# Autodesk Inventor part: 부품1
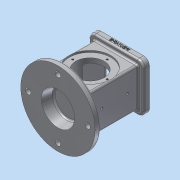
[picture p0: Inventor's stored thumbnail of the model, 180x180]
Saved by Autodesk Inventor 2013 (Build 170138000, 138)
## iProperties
Created: 2018-10
Part Number: 부품1
Material: 알루미늄 6061
Document SubType Name: Modeling
Designer: Administrator
Density: 2.71 g/cm^3
Mass: 988.226 g
Surface Area: 743.901 cm^2
Volume: 364.659 cm^3
Author: Administrator
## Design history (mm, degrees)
sketch "스케치1"
  geometry: L1 (37, 33)-(-37, 33); L2 (-37, 33)-(-37, -33); L3 (-37, -33)-(37, -33); L4 (37, -33)-(37, 33); L5 (37, 33)-(-37, -33); L6 (-37, 33)-(37, -33); 1 further point
  constraints: 12 end point, 2 midpoint, 2 parallel, 1 horizontal, 1 perpendicular
  dimensions: "d0" = 74 distance of L3.end L2.end; "d1" = 66 distance of L2.end L1.end
extrude "돌출1" new body sketch "스케치1" stored distance "d2" = 108; taper "d3" = 0 deg
sketch "스케치2"
  geometry: L1 (-37, -33)-(37, -33) reference; L2 (37, -33)-(37, 33) reference; L3 (37, 33)-(-37, 33) reference; L4 (-37, 33)-(-37, -33) reference; L5 (-46, -41)-(46, -41); L6 (46, -41)-(46, 41); L7 (46, 41)-(-46, 41); L8 (-46, 41)-(-46, -41); L9 (-46, -41)-(46, 41); L10 (46, -41)-(-46, 41); 1 further point
  constraints: 12 end point, 2 midpoint, 2 parallel, 1 horizontal, 1 perpendicular
  dimensions: "d4" = 92 distance of L7.end L6.end; "d5" = 82 distance of L6.end L5.end
extrude "돌출2" join sketch "스케치2" distance "d6" = 10; taper "d7" = 0 deg
sketch "스케치3"
  geometry: L1 (37, 33)-(-37, 33) reference; L2 (-37, 33)-(-37, -33) reference; L3 (-37, -33)-(37, -33) reference; L4 (37, -33)-(37, 33) reference; C1 r 62.5 at (0, 0); 1 further point
  constraints: 1 centre point, 1 coincident
  dimensions: "d8" = 125 diameter of C1
extrude "돌출3" join sketch "스케치3" distance "d9" = 10; taper "d10" = 0 deg
node "작업 평면1"
sketch "스케치4"
  geometry: C1 r 35 at (0, 0); 1 further point
  constraints: 1 centre point, 1 coincident
  dimensions: "d12" = 70 diameter of C1
extrude "돌출4" cut sketch "스케치4" distance "d13" = 3; taper "d14" = 0 deg
sketch "스케치5"
  geometry: C1 r 35 at (0, 0) reference; C2 r 24 at (0, 0)
  constraints: 1 centre point, 1 coincident
  dimensions: "d15" = 48 diameter of C2
extrude "돌출5" cut sketch "스케치5" stored distance "d16" = 3; taper "d17" = 0 deg
sketch "스케치6" dims "d18" = 58
  geometry: C1 r 35 at (0, 0) reference; 2 further points
  constraints: 2 vertical alignment, 1 coincident, 2 other
hole "구멍1" sketch "스케치6" at (0, 29) diameter "d19" = 3.242; stored, may be unused: countersink angle "d23" = 90 deg, drill point angle "d25" = 118 deg; dims "d20" = 4, "d21" = 4, "d22" = 2, "d24" = 6
sketch "스케치7"
  geometry: L1 (-26, -26)-(26, -26); L2 (26, -26)-(26, 26); L3 (26, 26)-(-26, 26); L4 (-26, 26)-(-26, -26); L5 (-26, -26)-(26, 26); L6 (26, -26)-(-26, 26); 1 further point
  constraints: 12 end point, 2 midpoint, 2 parallel, 1 horizontal, 1 perpendicular
  dimensions: "d29" = 52 distance of L3.end L2.end; "d30" = 52 distance of L2.end L1.end
extrude "돌출6" cut sketch "스케치7" distance "d31" = 8; taper "d32" = 0 deg
sketch "스케치8"
  geometry: L1 (-22, -22)-(22, -22); L2 (22, -22)-(22, 22); L3 (22, 22)-(-22, 22); L4 (-22, 22)-(-22, -22); L5 (-22, -22)-(22, 22); L6 (22, -22)-(-22, 22); 1 further point
  constraints: 12 end point, 2 midpoint, 2 parallel, 1 horizontal, 1 perpendicular
  dimensions: "d33" = 44 distance of L3.end L2.end; "d34" = 44 distance of L2.end L1.end
extrude "돌출7" cut sketch "스케치8" distance "d35" = 74; taper "d36" = 0 deg
sketch "스케치9"
  geometry: L1 (-46, 44)-(-46, 54) reference; L2 (-46, 54)-(-26, 54) reference; L3 (-26, 54)-(-26, 46) reference; L4 (-26, 46)-(-22, 46) reference; L5 (-22, 46)-(-22, 9.592) reference; L6 (-22, -9.592)-(-22, -28) reference; L7 (-22, -28)-(22, -28) reference; L8 (22, -28)-(22, -9.592) reference; L9 (22, 9.592)-(22, 46) reference; L10 (22, 46)-(26, 46) reference; L11 (26, 46)-(26, 54) reference; L12 (26, 54)-(46, 54) reference; L13 (46, 54)-(46, 44) reference; L14 (46, 44)-(37, 44) reference; L15 (37, 44)-(37, -44) reference; L16 (37, -44)-(62.5, -44) reference; L17 (62.5, -44)-(62.5, -54) reference; L18 (62.5, -54)-(-62.5, -54) reference; L19 (-62.5, -54)-(-62.5, -44) reference; L20 (-62.5, -44)-(-37, -44) reference; L21 (-37, -44)-(-37, 44) reference; L22 (-37, 44)-(-46, 44) reference; L23 (-28, -54)-(-24.826, -36); L24 (-24.826, -36)-(0, -36); L25 (0, -36)-(0, -54); L26 (-28, -54)-(0, -54); A1 r 24 centre (0, 0) between (-22, 9.592) and (-22, -9.592) reference; A2 r 24 centre (0, 0) between (22, -9.592) and (22, 9.592) reference; 1 further point
  constraints: 8 end point, 1 collinear, 1 midpoint, 1 parallel, 1 point on line
  dimensions: "d37" = 18 distance between parallel lines of L24 L26; "d39" = 80 deg angle of L26 L23; "d41" = 18 distance of L24.end L25.end; "d42" = 56 diameter of L23.start L25
revolve "회전1" sketch "스케치9" stored, may be unused: angle "d43" = 90 deg
sketch "스케치10"
  geometry: 5 further points
  dimensions: "d44" = 72 distance of point (36, 31) point (-36, 31); "d46" = 62 distance of point (36, -31) point (36, 31); "d47" = 36 horizontal distance of point (36, 31) point (0, 0); "d48" = 31 vertical distance of point (36, 31) point (0, 0); "d49" = 36 horizontal distance of point (0, 0) point (-36, 31); "d50" = 31 vertical distance of point (36, -31) point (0, 0); "d51" = 72 distance of point (36, -31) point (-36, -31); "d52" = 36 horizontal distance of point (0, 0) point (-36, -31)
hole "구멍2" sketch "스케치10" at (-36, 31), (36, 31), (36, -31), (-36, -31) diameter "d53" = 3.242; stored, may be unused: countersink angle "d57" = 90 deg, drill point angle "d59" = 118 deg; dims "d54" = 4, "d55" = 4, "d56" = 2, "d58" = 6
sketch "스케치11" dims "d60" = 100
  geometry: C1 r 62.5 at (0, 0) reference; 2 further points
  constraints: 2 vertical alignment, 1 coincident, 2 other
hole "구멍3" sketch "스케치11" at (0, 50) diameter "d61" = 9; stored, may be unused: countersink angle "d65" = 90 deg, drill point angle "d67" = 118 deg; dims "d62" = 4, "d63" = 4, "d64" = 2, "d66" = 6
fillet "모깎기1" dims "d71" = 10
node "작업 평면2"
sketch "스케치12"
  geometry: L1 (36, 44)-(-36, 44) reference; L2 (-36, 54)-(-36, 44) reference; L3 (-36, 54)-(36, 54) reference; L4 (36, 54)-(36, 44) reference; L5 (-47.173, -54)-(-47.173, -44) reference; L6 (-47.173, -44)-(47.173, -44) reference; L7 (47.173, -44)-(47.173, -54) reference; L8 (47.173, -54)-(-47.173, -54) reference; L9 (-46, 54)-(-46, 44) reference; 2 further points
  constraints: 1 vertical alignment, 1 other
  dimensions: "d74" = 4 distance from line of L3 point (0, 50)
feature "엠보싱1" sketch "스케치12" dims "d0" = 74, "d1" = 66, "d75" = 0.5, "d76" = 0
fillet "모깎기2" dims "d77" = 3
fillet "모깎기3" dims "d78" = 3
chamfer "모따기1" distance "d79" = 1; stored, may be unused: second distance "d80" = 2, angle "d81" = 45 deg
fillet "모깎기4" dims "d82" = 3
node "작업 평면3"
sketch "스케치14"
  geometry: L1 (-54, -62.5)-(-54, 62.5) reference; 3 further points
  constraints: 2 horizontal alignment
  dimensions: "d84" = 37 distance from line of L1 point (-17, 0); "d85" = 43 distance of point (26, 0) point (-17, 0)
hole "구멍4" sketch "스케치14" at (26, 0), (-17, 0) diameter "d86" = 4.134; stored, may be unused: countersink angle "d90" = 90 deg, drill point angle "d92" = 118 deg; dims "d87" = 20, "d88" = 4, "d89" = 2, "d91" = 20
node "솔리드1"
mirror "대칭1"
pattern_circular "원형 패턴1" dims angle "d27" = 360 deg
mirror "대칭2"
pattern_circular "원형 패턴2" dims angle "d69" = 360 deg
node "절단 모서리 투영1"
node "절단 모서리 투영2"
other parameters: "d11" = 33, "d72" = 41, "d83" = 37
